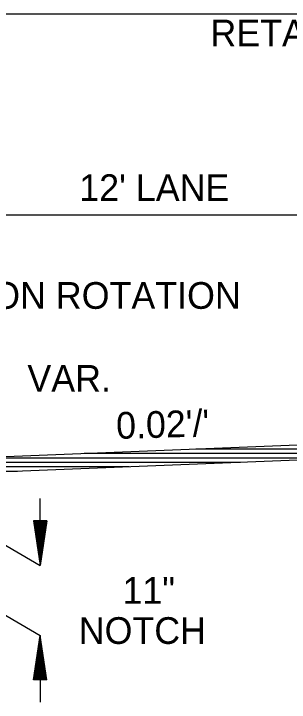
# Model space of a CAD drawing. Extents: x 1955768 to 1955917, y 566446 to 566546.
# Drawn here: x 1955830.51 to 1955836.69, y 566514.26 to 566529.71 of the extents above; entities that cross this region are included whole.
import ezdxf

# ---------------------------------------------------------------- set-up
doc = ezdxf.new("R2010")
doc.units = 0
doc.layers.add('R_Border', color=7, linetype='Continuous')
doc.layers.add('R_Grid', color=7, linetype='Continuous')

msp = doc.modelspace()

# ---------------------------------------------------------------- linework, layer by layer
at = {"layer": 'R_Border'}
for p, q in [((1955827.673, 566519.668), (1955839.673, 566520.148)), ((1955834.595, 566519.945), (1955844.75, 566519.945)), ((1955827.587, 566519.325), (1955839.673, 566519.808)), ((1955829.595, 566519.745), (1955838.097, 566519.745)), ((1955832.095, 566519.845), (1955847.25, 566519.845)), ((1955827.08, 566519.645), (1955835.597, 566519.645)), ((1955822.261, 566519.445), (1955830.597, 566519.445)), ((1955824.671, 566519.545), (1955833.097, 566519.545)), ((1955827.673, 566519.328), (1955831.107, 566517.328)), ((1955827.673, 566517.757), (1955831.107, 566515.757))]:
    msp.add_line(p, q, dxfattribs=at)
at = {"layer": 'R_Grid'}
for p, q in [((1955827.673, 566529.708), (1955851.672, 566529.708)), ((1955827.673, 566525.195), (1955839.673, 566525.195)), ((1955831.107, 566517.328), (1955831.107, 566518.828)), ((1955830.957, 566518.328), (1955831.107, 566517.328)), ((1955831.257, 566518.328), (1955830.957, 566518.328)), ((1955830.982, 566518.328), (1955831.107, 566517.495)), ((1955831.008, 566518.328), (1955831.107, 566517.667)), ((1955831.033, 566518.328), (1955831.107, 566517.834)), ((1955831.058, 566518.328), (1955831.107, 566518.003)), ((1955831.084, 566518.328), (1955831.107, 566518.17)), ((1955831.257, 566518.328), (1955831.107, 566517.328)), ((1955831.156, 566518.328), (1955831.107, 566518.003)), ((1955831.207, 566518.328), (1955831.107, 566517.667)), ((1955831.232, 566518.328), (1955831.107, 566517.495)), ((1955831.182, 566518.328), (1955831.107, 566517.834)), ((1955831.131, 566518.328), (1955831.107, 566518.17)), ((1955830.957, 566514.757), (1955831.107, 566515.757)), ((1955831.107, 566515.757), (1955831.107, 566514.257)), ((1955831.257, 566514.757), (1955831.107, 566515.757)), ((1955830.982, 566514.757), (1955831.107, 566515.59)), ((1955831.232, 566514.757), (1955831.107, 566515.59)), ((1955831.008, 566514.757), (1955831.107, 566515.418)), ((1955831.207, 566514.757), (1955831.107, 566515.418)), ((1955831.033, 566514.757), (1955831.107, 566515.252)), ((1955831.182, 566514.757), (1955831.107, 566515.252)), ((1955831.058, 566514.757), (1955831.107, 566515.082)), ((1955831.156, 566514.757), (1955831.107, 566515.082)), ((1955831.084, 566514.757), (1955831.107, 566514.915)), ((1955831.131, 566514.757), (1955831.107, 566514.915)), ((1955831.257, 566514.757), (1955830.957, 566514.757))]:
    msp.add_line(p, q, dxfattribs=at)

# ---------------------------------------------------------------- texts
at = {"layer": 'R_Border'}
for s, p in [('RETAIN AND OVERLAY', (1955834.922, 566528.976)), ("12' LANE", (1955831.982, 566525.505)), ('POINT OF C.L. TRANSITION ROTATION', (1955820.669, 566523.086)), ('VAR.', (1955830.819, 566521.225)), ('11" ', (1955832.95, 566516.466)), ('NOTCH', (1955831.97, 566515.566))]:
    msp.add_text(s, height=0.6, dxfattribs=at).set_placement(p)
msp.add_text("0.02'/'", height=0.6, rotation=1.6022, dxfattribs=at).set_placement((1955832.816, 566520.166))

doc.saveas('drawing.dxf')
